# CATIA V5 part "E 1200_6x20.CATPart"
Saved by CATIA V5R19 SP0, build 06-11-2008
Nomenclature: E 1200_6x20
Description: PART-E 1200_6x20-DESC
Material "Steel": density 7860 kg/m3, Young's modulus 2e+11 Pa, Poisson ratio 0.266, thermal expansion 1.17e-05 1/K
Bounding box of the stored display mesh (mm): x -5 to 5, y -4.99 to 4.99, z -6 to 20
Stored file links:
  G:\UTB\Kombinované\Bakalářská práce\Catia\FORMA\E 1200_6x20.CATPart
  D:\Aplikace\CATIA\Nová složka\win_b64\startup\materials\Catalog.CATMaterial
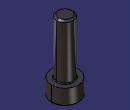
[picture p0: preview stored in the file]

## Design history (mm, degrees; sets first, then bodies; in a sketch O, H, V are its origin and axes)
Body1 "E 1200_6x20" (main body)
  Solid1: solid without history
